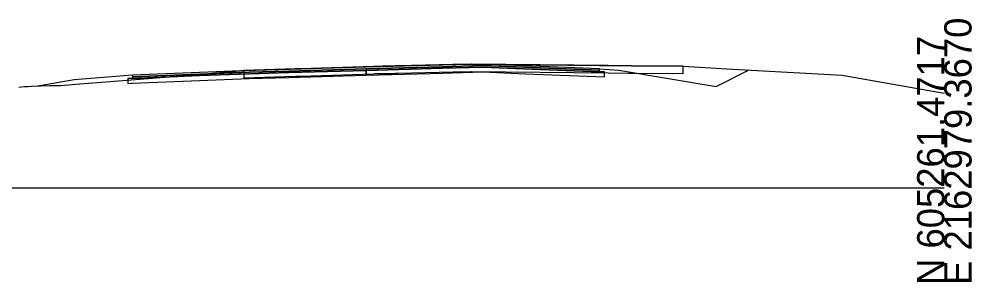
# Model space of a CAD drawing. Extents: x -26 to 1303, y -10 to 12038.
# Drawn here: x 204.9 to 302.8, y 8990.3 to 9017.3 of the extents above; entities that cross this region are included whole.
import ezdxf

# ---------------------------------------------------------------- set-up
doc = ezdxf.new("R2010")
doc.units = 0
for name, color, linetype in [('RD_GPK_XS_Cell', 7, 'Continuous'), ('RD_XS_Base', 7, 'Continuous'), ('RD_XS_ExGround', 7, 'Continuous'), ('RD_XS_ExPaveRet', 7, 'Continuous'), ('RD_XS_Greenside', 7, 'Continuous'), ('RD_XS_Pave', 7, 'Continuous'), ('RD_XS_PaveOvlay_CP', 7, 'Continuous'), ('RD_XS_TieSlope', 7, 'Continuous')]:
    doc.layers.add(name, color=color, linetype=linetype)

msp = doc.modelspace()

# ---------------------------------------------------------------- linework, layer by layer
at = {"layer": 'RD_GPK_XS_Cell'}
msp.add_line((150, 9000), (300, 9000), dxfattribs=at)
at = {"layer": 'RD_XS_Base'}
for p, q in [((248.418, 9012.279), (240.553, 9012.058)), ((252.553, 9012.395), (248.418, 9012.279)), ((256.773, 9012.226), (252.553, 9012.395)), ((223.432, 9011.517), (216.552, 9011.241)), ((228.553, 9011.722), (223.432, 9011.517)), ((232.626, 9011.836), (228.553, 9011.722)), ((228.553, 9011.222), (232.626, 9011.336)), ((240.553, 9012.058), (232.626, 9011.836)), ((232.626, 9011.336), (240.553, 9011.558)), ((240.553, 9012.164), (240.553, 9012.217)), ((240.553, 9012.217), (240.553, 9011.995)), ((240.553, 9012.058), (240.553, 9012.164)), ((240.553, 9012.058), (240.553, 9012.058)), ((240.553, 9012.058), (240.553, 9012.058)), ((240.553, 9011.89), (240.553, 9012.058)), ((240.553, 9011.995), (240.553, 9011.558)), ((240.553, 9011.558), (240.553, 9011.89)), ((240.553, 9011.558), (248.418, 9011.779)), ((248.418, 9011.779), (252.553, 9011.895)), ((252.553, 9011.895), (256.951, 9011.719)), ((264.553, 9011.915), (256.773, 9012.226)), ((256.951, 9011.719), (265.054, 9011.395)), ((264.733, 9011.908), (264.553, 9011.915)), ((265.054, 9011.895), (264.733, 9011.908)), ((265.054, 9011.716), (265.054, 9011.895)), ((265.054, 9011.395), (265.054, 9011.716)), ((216.399, 9011.235), (216.052, 9011.221)), ((216.052, 9011.221), (216.052, 9011.069)), ((216.052, 9011.069), (216.052, 9010.721)), ((216.052, 9010.721), (216.399, 9010.735)), ((216.552, 9011.241), (216.399, 9011.235)), ((216.399, 9010.735), (216.552, 9010.741)), ((216.552, 9010.741), (223.432, 9011.017)), ((223.432, 9011.017), (228.553, 9011.222))]:
    msp.add_line(p, q, dxfattribs=at)
at = {"layer": 'RD_XS_ExGround'}
msp.add_lwpolyline([(204.843, 9010.332), (205.439, 9010.391), (205.808, 9010.399), (206.147, 9010.431), (208.082, 9010.5), (209.173, 9010.503), (211.132, 9010.669), (213.802, 9010.875), (218.162, 9011.211), (227.977, 9012.031), (233.847, 9012.22), (241.878, 9012.487), (242.311, 9012.5), (242.363, 9012.499), (243.313, 9012.485), (243.58, 9012.514), (243.807, 9012.529), (249.699, 9012.666), (249.736, 9012.659), (251.415, 9012.7), (267.834, 9012.532), (273.142, 9012.485), (277.63, 9012.216), (289.487, 9011.56), (300, 9009.723)], dxfattribs=at)
at = {"layer": 'RD_XS_ExPaveRet'}
for points in [[(251.437, 9012.7), (251.418, 9012.7), (251.414, 9012.7), (251.404, 9012.7), (249.722, 9012.659), (249.684, 9012.666), (249.488, 9012.661), (243.807, 9012.529), (243.796, 9012.528), (243.58, 9012.514), (243.576, 9012.514), (243.313, 9012.485), (243.297, 9012.486), (242.424, 9012.499), (242.358, 9012.497), (242.266, 9012.498), (241.487, 9012.474), (241.303, 9012.468), (233.847, 9012.221), (233.29, 9012.203), (227.977, 9012.031), (227.977, 9011.333), (227.977, 9011.281), (233.29, 9011.452), (233.847, 9011.47), (241.303, 9011.717), (241.487, 9011.724), (242.266, 9011.748), (242.358, 9011.747), (242.424, 9011.749), (243.297, 9011.736), (243.313, 9011.735), (243.576, 9011.764), (243.58, 9011.764), (243.796, 9011.778), (243.807, 9011.779), (249.488, 9011.911), (249.684, 9011.916), (249.722, 9011.909), (251.404, 9011.95), (251.414, 9011.95), (251.418, 9011.95), (251.437, 9011.95), (265.443, 9011.807), (267.558, 9011.785), (267.834, 9011.782), (273.142, 9011.735), (273.142, 9011.735), (273.142, 9012.452), (273.142, 9012.485), (273.142, 9012.485), (267.834, 9012.532), (267.558, 9012.535), (265.443, 9012.557), (251.437, 9012.7)], [(251.437, 9012.7), (251.418, 9012.7), (251.414, 9012.7), (251.404, 9012.7), (249.722, 9012.659), (249.684, 9012.666), (249.488, 9012.661), (243.807, 9012.529), (243.796, 9012.528), (243.58, 9012.514), (243.576, 9012.514), (243.313, 9012.485), (243.297, 9012.486), (242.424, 9012.499), (242.358, 9012.497), (242.266, 9012.498), (241.487, 9012.474), (241.303, 9012.468), (233.847, 9012.221), (233.29, 9012.203), (227.977, 9012.031), (227.977, 9011.333), (227.977, 9011.281), (233.29, 9011.452), (233.847, 9011.47), (241.303, 9011.717), (241.487, 9011.724), (242.266, 9011.748), (242.358, 9011.747), (242.424, 9011.749), (243.297, 9011.736), (243.313, 9011.735), (243.576, 9011.764), (243.58, 9011.764), (243.796, 9011.778), (243.807, 9011.779), (249.488, 9011.911), (249.684, 9011.916), (249.722, 9011.909), (251.404, 9011.95), (251.414, 9011.95), (251.418, 9011.95), (251.437, 9011.95), (265.443, 9011.807), (267.558, 9011.785), (267.834, 9011.782), (273.142, 9011.735), (273.142, 9012.452), (273.142, 9012.485), (267.834, 9012.532), (267.558, 9012.535), (265.443, 9012.557), (251.437, 9012.7)]]:
    msp.add_lwpolyline(points, dxfattribs=at)
at = {"layer": 'RD_XS_Greenside'}
for p, q in [((266.554, 9012.073), (276.554, 9010.407)), ((276.554, 9010.407), (279.944, 9012.102)), ((210.552, 9011.079), (206.805, 9010.454))]:
    msp.add_line(p, q, dxfattribs=at)
at = {"layer": 'RD_XS_Pave'}
for p, q in [((240.553, 9012.376), (232.626, 9012.154)), ((248.418, 9012.597), (240.553, 9012.376)), ((248.418, 9012.438), (240.553, 9012.217)), ((240.553, 9012.217), (248.418, 9012.438)), ((240.553, 9012.058), (248.418, 9012.279)), ((252.553, 9012.713), (248.418, 9012.597)), ((252.553, 9012.554), (248.418, 9012.438)), ((248.418, 9012.438), (252.553, 9012.554)), ((248.418, 9012.279), (252.553, 9012.395)), ((256.773, 9012.544), (252.553, 9012.713)), ((256.773, 9012.385), (252.553, 9012.554)), ((252.553, 9012.554), (256.773, 9012.385)), ((252.553, 9012.395), (256.773, 9012.226)), ((264.553, 9012.233), (256.773, 9012.544)), ((264.553, 9012.074), (256.773, 9012.385)), ((256.773, 9012.385), (264.553, 9012.074)), ((264.553, 9012.176), (264.553, 9012.233)), ((223.432, 9011.835), (216.552, 9011.559)), ((223.432, 9011.676), (216.552, 9011.4)), ((216.552, 9011.4), (223.432, 9011.676)), ((216.552, 9011.559), (216.552, 9011.511)), ((216.552, 9011.241), (223.432, 9011.517)), ((216.552, 9011.511), (216.552, 9011.4)), ((216.552, 9011.4), (216.552, 9011.352)), ((216.552, 9011.352), (216.552, 9011.241)), ((228.553, 9012.04), (223.432, 9011.835)), ((228.553, 9011.881), (223.432, 9011.676)), ((223.432, 9011.676), (228.553, 9011.881)), ((223.432, 9011.517), (228.553, 9011.722)), ((232.626, 9012.154), (228.553, 9012.04)), ((232.626, 9011.995), (228.553, 9011.881)), ((228.553, 9011.881), (232.626, 9011.995)), ((228.553, 9011.722), (232.626, 9011.836)), ((240.553, 9012.217), (232.626, 9011.995)), ((232.626, 9011.995), (240.553, 9012.217)), ((232.626, 9011.836), (240.553, 9012.058)), ((240.553, 9012.164), (240.553, 9012.217)), ((240.553, 9012.217), (240.553, 9012.217)), ((240.553, 9012.217), (240.553, 9012.217)), ((240.553, 9012.217), (240.553, 9012.164)), ((240.553, 9012.058), (240.553, 9012.164)), ((240.553, 9012.164), (240.553, 9012.058)), ((240.553, 9012.058), (240.553, 9012.058)), ((240.553, 9012.058), (240.553, 9012.058)), ((256.773, 9012.226), (264.553, 9011.915)), ((264.553, 9012.074), (264.553, 9012.176)), ((264.553, 9012.017), (264.553, 9012.074)), ((264.553, 9011.915), (264.553, 9012.017))]:
    msp.add_line(p, q, dxfattribs=at)
at = {"layer": 'RD_XS_PaveOvlay_CP'}
for p, q in [((240.553, 9012.376), (232.626, 9012.154)), ((248.418, 9012.597), (240.553, 9012.376)), ((252.553, 9012.713), (248.418, 9012.597)), ((256.773, 9012.544), (252.553, 9012.713)), ((264.553, 9012.233), (256.773, 9012.544)), ((223.432, 9011.835), (216.552, 9011.559)), ((228.553, 9012.04), (223.432, 9011.835)), ((232.626, 9012.154), (228.553, 9012.04))]:
    msp.add_line(p, q, dxfattribs=at)
at = {"layer": 'RD_XS_TieSlope'}
for p, q in [((264.553, 9012.233), (266.554, 9012.073)), ((216.552, 9011.559), (210.552, 9011.079))]:
    msp.add_line(p, q, dxfattribs=at)

# ---------------------------------------------------------------- texts
at = {"layer": 'RD_GPK_XS_Cell'}
for s, p in [('E 2162979.3670', (302.8, 8990)), ('N 605261.4717', (300, 8990))]:
    msp.add_text(s, height=2.8, rotation=90, dxfattribs=at).set_placement(p)

doc.saveas('drawing.dxf')
